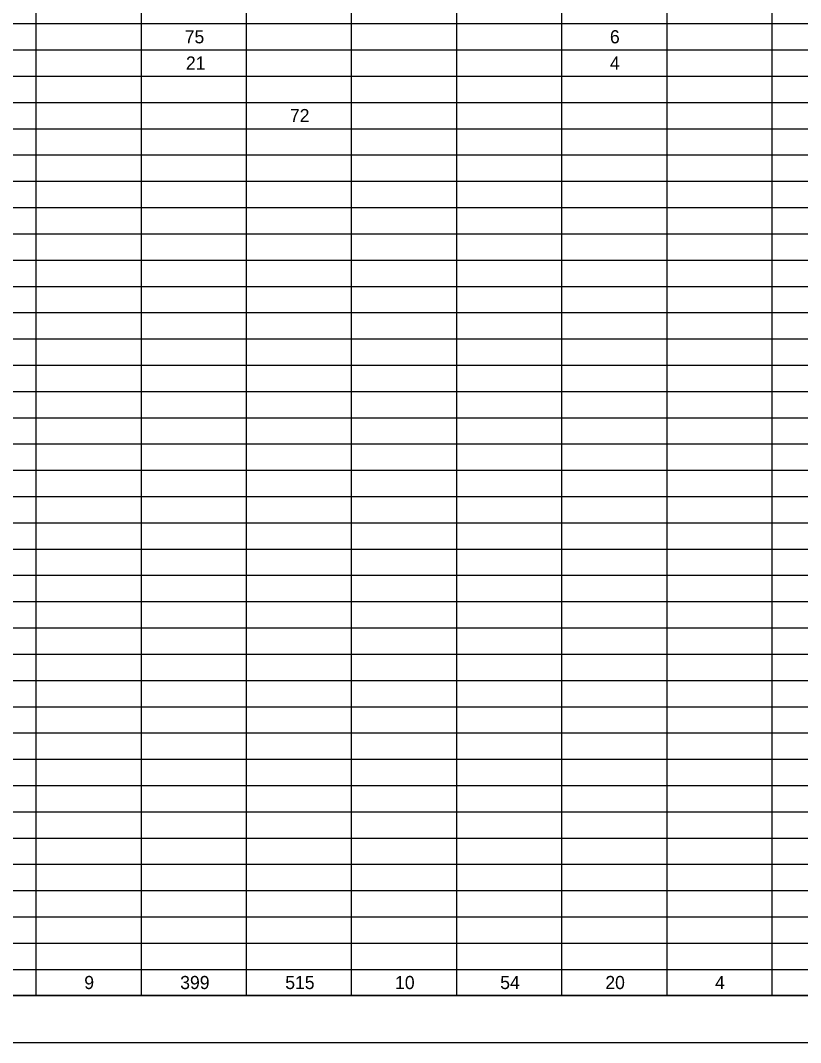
# Model space of a CAD drawing. Extents: x 0 to 34, y 0 to 22.
# Drawn here: x 17.28 to 25.59, y 0 to 10.89 of the extents above; entities that cross this region are included whole.
import ezdxf

# ---------------------------------------------------------------- set-up
doc = ezdxf.new("R2010")
doc.units = 0
for name, color, linetype in [('SH_Border', 7, 'Continuous'), ('SH_Cut_Line', 7, 'Continuous'), ('SH_Text', 7, 'Continuous')]:
    doc.layers.add(name, color=color, linetype=linetype)

msp = doc.modelspace()

# ---------------------------------------------------------------- linework, layer by layer
at = {"layer": 'SH_Border'}
msp.add_lwpolyline([(1.5, 21.5), (33.5, 21.5), (33.5, 0.5), (1.5, 0.5)], close=True, dxfattribs=at)
at = {"layer": 'SH_Cut_Line'}
msp.add_lwpolyline([(0, 0), (34, 0), (34, 22), (0, 22)], close=True, dxfattribs=at)
at = {"layer": 'SH_Text'}
for p, q in [((17.444, 21.5), (17.444, 0.5)), ((18.564, 21.5), (18.564, 0.5)), ((19.684, 21.5), (19.684, 0.5)), ((20.804, 21.5), (20.804, 0.5)), ((21.924, 21.5), (21.924, 0.5)), ((23.044, 21.5), (23.044, 0.5)), ((24.164, 21.5), (24.164, 0.5)), ((25.284, 21.5), (25.284, 0.5)), ((1.5, 10.86), (32.004, 10.86)), ((1.5, 10.58), (32.004, 10.58)), ((1.5, 10.3), (32.004, 10.3)), ((1.5, 10.02), (32.004, 10.02)), ((1.5, 9.74), (32.004, 9.74)), ((1.5, 9.46), (32.004, 9.46)), ((1.5, 9.18), (32.004, 9.18)), ((1.5, 8.9), (32.004, 8.9)), ((1.5, 8.62), (32.004, 8.62)), ((1.5, 8.34), (32.004, 8.34)), ((1.5, 8.06), (32.004, 8.06)), ((1.5, 7.78), (32.004, 7.78)), ((1.5, 7.5), (32.004, 7.5)), ((1.5, 7.22), (32.004, 7.22)), ((1.5, 6.94), (32.004, 6.94)), ((1.5, 6.66), (32.004, 6.66)), ((1.5, 6.38), (32.004, 6.38)), ((1.5, 6.1), (32.004, 6.1)), ((1.5, 5.82), (32.004, 5.82)), ((1.5, 5.54), (32.004, 5.54)), ((1.5, 5.26), (32.004, 5.26)), ((1.5, 4.98), (32.004, 4.98)), ((1.5, 4.7), (32.004, 4.7)), ((1.5, 4.42), (32.004, 4.42)), ((1.5, 4.14), (32.004, 4.14)), ((1.5, 3.86), (32.004, 3.86)), ((1.5, 3.58), (32.004, 3.58)), ((1.5, 3.3), (32.004, 3.3)), ((1.5, 3.02), (32.004, 3.02)), ((1.5, 2.74), (32.004, 2.74)), ((1.5, 2.46), (32.004, 2.46)), ((1.5, 2.18), (32.004, 2.18)), ((1.5, 1.9), (32.004, 1.9)), ((1.5, 1.62), (32.004, 1.62)), ((1.5, 1.34), (32.004, 1.34)), ((1.5, 1.06), (32.004, 1.06)), ((1.5, 0.78), (32.004, 0.78)), ((1.5, 0.5), (32.004, 0.5))]:
    msp.add_line(p, q, dxfattribs=at)

# ---------------------------------------------------------------- texts
for s, p in [('75', (19.029, 10.65)), ('6', (23.559, 10.65)), ('21', (19.042, 10.37)), ('4', (23.559, 10.37)), ('72', (20.15, 9.81)), ('9', (17.959, 0.57)), ('399', (18.981, 0.57)), ('515', (20.1, 0.57)), ('10', (21.27, 0.57)), ('54', (22.39, 0.57)), ('20', (23.51, 0.57)), ('4', (24.679, 0.57))]:
    msp.add_text(s, height=0.14, dxfattribs=at).set_placement(p)

doc.saveas('drawing.dxf')
